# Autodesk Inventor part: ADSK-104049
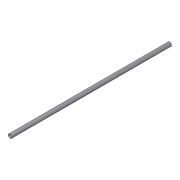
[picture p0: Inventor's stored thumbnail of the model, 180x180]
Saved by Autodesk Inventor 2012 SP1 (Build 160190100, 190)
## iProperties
Shininess: 0.0
Created: 2000-11
Part Number: ADSK-104049
Description: MECH TUBING 2-3/8" OD. x 2" ID. x 90" LONG
Document SubType Name: Modeling
Stock Number: ADSK-104049
Density: 1 g/cm^3
Material: Default
Density: 0.0
Volumn: 0.0
Area: 0.0
PropertySet Name: Model Information
Control State: 0
Master: False
Checked Out: False
Author: gao
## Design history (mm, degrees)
node "Extrusion1" dims "d2" = 1143, "d3" = 0
  sketch "Sketch1"
    geometry: C1 r 24.625 at (-2.242, -1.316); C2 r 30.162 at (-2.242, -1.316)
    constraints: 2 centre point, 1 coincident
    dimensions: "d0" = 49.2506 diameter of C1; "d1" = 60.325 diameter of C2
node "Extrusion2" dims "d5" = 50.8, "d6" = 0
  sketch "Sketch2"
    geometry: C1 r 24.625 at (0, 0) reference; C2 r 30.162 at (0, 0) reference; C3 r 26.194 at (0, 0)
    constraints: 1 centre point, 1 coincident
    dimensions: "d4" = 52.3875 diameter of C3
workplane "Work Plane1"
node "Mirror1"
body "Solid1"
other parameters: "d7" = 0
